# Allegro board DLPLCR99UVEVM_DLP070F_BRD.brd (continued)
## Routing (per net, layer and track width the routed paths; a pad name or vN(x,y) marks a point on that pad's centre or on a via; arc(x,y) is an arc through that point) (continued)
I2C_SCL_3P3V: length 123.7
  TOP w0.203: 115.04,13.7 114.54,14.2 114.54,17.05 114.43,17.17 R7.1 v1(112.81,18.78) ; 115.04,13.7 U17.8 ; 115.04,13.7 114.98,13.64 114.93,13.64 114.22,12.93 J5.1 ; v1(126.18,109.83) 126.66,110.31 126.66,110.51 127.93,111.78 127.93,113.31 127.17,114.07 J2.14
  LY4-SIG w0.165: v1(112.81,18.78) 116.26,18.78 128.19,30.71 128.19,90.63 127.52,91.29 127.52,107.42 126.18,108.76 v1(126.18,109.83)
I2C_SDA_3P3V: length 120.9
  TOP w0.203: v1(125.82,110.84) 125.82,112.39 126.79,113.36 126.79,114.83 126.67,114.95 J2.15 ; J5.2 115.47,10.28 114.85,10.9 114.85,12.75 115.16,13.05 115.43,13.05 115.43,13.05 U17.7 118.76,13.05 119.35,13.64 119.35,16.71 119.38,16.75 R6.1 v1(119.38,18.93)
  LY4-SIG w0.165: v1(119.38,18.93) 129.61,29.16 129.61,106.32 126.99,108.94 126.99,110.59 126.74,110.84 v1(125.82,110.84)
LATCH_CLEAR_Z: length 29.3
  TOP w0.203: R56.1 108.98,94 108.6,94.39 U18.6 106.96,94.39 v1(106.44,93.88)
  LY6-SIG w0.119: v1(106.44,93.88) 107.2,94.64 107.2,110.01 110.25,113.05 v1(111.9,113.05)
  BOTTOM w0.203: v1(111.9,113.05) 112.18,113.33 J4.8
LS_CLK_N: length 128.3
  TOP w0.127: J1.11 84.86,115.32 84.79,115.25 84.79,115.1 84.87,115.02 84.87,114.16 84.6,113.89 84.6,111.99 84.88,111.71 86.13,111.71 86.5,111.33 86.5,110.9 86.63,110.77 86.71,110.77 v1(87.17,110.31)
  LY4-SIG w0.127: v1(87.75,14.23) 87.19,14.79 87.19,15.05 93.84,21.71 93.84,22.48 93.6,22.73 93.6,23.59 93.84,23.84 93.84,25.22 93.61,25.45 93.61,25.86 93.84,26.1 93.84,27.76 93.61,27.99 93.61,28.4 93.84,28.64 93.84,30.05 93.44,30.45 93.44,31.09 93.82,31.46 93.82,32.62 93.54,32.9 93.54,33.83 101.24,41.53 101.24,54.38 104.36,57.5 104.36,84.59 103.05,85.9 103.05,93.55 101.18,95.42 99.04,95.42 97.41,93.79 93.59,93.79 89.63,97.74 89.63,104.26 86.56,107.34 86.56,109.87 86.69,110 86.86,110 86.88,110.02 86.88,110.02 v1(87.17,110.31)
  BOTTOM w0.508: U16.A25 v1(87.75,14.23)
LS_CLK_P: length 126.7
  TOP w0.127: J1.12 84.36,115.32 84.53,115.15 84.53,115 84.61,114.92 84.61,114.27 84.34,114 84.34,111.88 84.77,111.45 86.02,111.45 86.25,111.23 v1(86.25,110.31)
  LY4-SIG w0.127: v1(86.48,15.5) 87.2,15.5 93.53,21.84 93.53,22.36 93.29,22.6 93.29,23.72 93.53,23.97 93.53,25.09 93.3,25.33 93.3,25.99 93.53,26.23 93.53,27.63 93.3,27.87 93.3,28.53 93.53,28.77 93.53,29.93 93.13,30.33 93.13,31.22 93.51,31.59 93.51,32.49 93.23,32.77 93.23,33.96 100.93,41.66 100.93,54.51 104.05,57.63 104.05,84.46 102.74,85.77 102.74,93.42 101.05,95.11 99.17,95.11 97.54,93.48 93.46,93.48 89.32,97.61 89.32,104.13 86.25,107.21 v1(86.25,110.31)
  BOTTOM w0.508: U16.B24 v1(86.48,15.5)
LS_RDATA_A: length 140.2
  TOP w0.203: J1.8 v1(86.36,114.63)
  LY4-SIG w0.165: v1(86.36,114.63) 86.36,116.55 87.11,117.3 93.22,117.3 93.97,118.05 93.97,120 93.22,120.75 84.07,120.75 83.35,120.04 83.35,113.51 81.6,111.76 81.6,111.5 80.51,110.41 80.51,107.31 83.51,104.32 83.51,90.3 95.37,78.43 95.37,58.44 93.95,57.02 93.95,54.46 97.27,51.13 97.27,42.65 90.82,36.19 90.82,23.52 87.88,20.58 v1(86.48,20.58)
  BOTTOM w0.508: U16.F24 v1(86.48,20.58)
LS_RDATA_B: length 135.1
  TOP w0.203: J2.7 130.67,115.24 130.83,115.09 130.83,113.64 130.24,113.05 130.24,112.22 130.52,111.94 130.73,111.94 v1(131.26,111.4)
  LY6-SIG w0.119: v1(131.26,111.4) 130.31,111.4 129.91,111.01 129.91,110.26 132.25,107.92 132.25,88.29 130.67,86.71 130.67,69.21 111.19,49.73 108.14,49.73 105.15,46.73 98.56,46.73 95.96,44.14 95.09,44.14 93.77,45.46 89.63,45.46 89.2,45.03 89.2,44.19 91.07,42.32 91.07,30.08 93.39,27.76 93.39,23.98 91.96,22.55 91.81,22.55 89.02,19.77 v1(89.02,18.04)
  BOTTOM w0.508: U16.D26 v1(89.02,18.04)
LS_RDATA_C: length 129.5
  TOP w0.203: J2.8 v1(130.17,114.63)
  LY6-SIG w0.119: v1(94.1,20.58) 95.3,20.58 98.24,23.52 98.24,27.74 92.34,33.63 92.34,43 93.35,44.01 94.39,44.01 94.86,43.53 96.05,43.53 98.62,46.1 105.71,46.1 106.9,47.29 109.64,47.29 110.28,47.93 111.22,47.93 131.44,68.15 131.44,85.72 133.11,87.4 133.11,110.24 131.37,111.99 130.57,111.99 129.51,113.05 129.51,113.97 130.17,114.63 v1(130.17,114.63)
  BOTTOM w0.508: U16.F30 v1(94.1,20.58)
LS_RDATA_D: length 132.5
  TOP w0.203: J2.9 129.67,115.08 129.61,115.01 129.61,112.93 129.86,112.67 129.86,112.09 130.17,111.78 130.17,111.32 130.55,110.95 v1(130.55,110.57)
  LY6-SIG w0.119: v1(130.55,110.57) 132.6,108.51 132.6,87.73 131.03,86.16 131.03,69.04 111.29,49.3 108.25,49.3 105.29,46.35 98.52,46.35 96.01,43.84 94.96,43.84 94.23,44.58 93.46,44.58 91.76,42.87 91.76,41.53 92.1,41.19 92.1,31.82 94.73,29.18 94.73,22.33 93.62,21.21 90.97,21.21 89.5,19.73 89.5,18.77 90.29,17.98 v1(90.29,16.77)
  BOTTOM w0.508: U16.C27 v1(90.29,16.77)
LS_WDATA_N: length 127.8
  TOP w0.127: v1(82.31,110.31) 82.01,110.62 82.01,112.09 83.24,113.32 83.24,115.2 83.36,115.32 J1.14
  LY4-SIG w0.127: v1(82.31,110.31) 81.81,109.81 81.81,108.35 87.82,102.34 87.82,93.07 99.69,81.2 99.69,42.45 92.2,34.95 92.2,34.11 92.47,33.83 92.47,32.87 92.2,32.59 92.2,31.57 92.47,31.29 92.47,30.17 92.2,29.9 92.2,28.7 92.37,28.53 92.37,27.87 92.2,27.69 92.2,26.16 92.37,25.99 92.37,25.33 92.2,25.15 92.2,23.62 92.37,23.45 92.37,22.79 92.2,22.61 92.2,22.36 85.97,16.13 85.97,15.14 87.63,13.49 90.59,13.49 90.94,13.84 90.94,14.58 90.34,15.19 89.5,15.19 89.02,14.71 89.02,14.43 89.22,14.23 v1(90.29,14.23)
  BOTTOM w0.508: U16.A27 v1(90.29,14.23)
LS_WDATA_P: length 127.3
  TOP w0.127: J1.15 82.86,115.32 82.98,115.2 82.98,113.42 81.75,112.19 81.75,110.67 v1(81.39,110.31)
  LY4-SIG w0.127: v1(81.39,110.31) 81.39,109.83 81.5,109.73 81.5,108.22 87.51,102.21 87.51,92.94 99.38,81.08 99.38,42.58 91.89,35.08 91.89,33.98 92.16,33.7 92.16,32.99 91.89,32.72 91.89,31.44 92.16,31.16 92.16,30.3 91.89,30.03 91.89,28.58 92.06,28.4 92.06,27.99 91.89,27.82 91.89,26.04 92.06,25.86 92.06,25.45 91.89,25.28 91.89,23.5 92.06,23.32 92.06,22.91 91.89,22.74 91.89,22.48 85.66,16.26 85.66,15.02 87.5,13.18 90.72,13.18 91.25,13.71 91.25,14.71 90.47,15.5 v1(89.02,15.5)
  BOTTOM w0.508: U16.B26 v1(89.02,15.5)
MBRST0: length 110
  TOP w0.203: J9.1 v1(3.32,13.36)
  LY4-SIG w0.165: v1(3.32,13.36) 6.37,10.31 44.57,10.31 47.11,7.77 66.13,7.77 68.98,10.62 68.98,14.12 67.96,15.14 67.96,15.75 74.9,22.68 77.11,22.68 78.22,23.8 87.72,23.8 88.49,24.56 88.49,27.66 v1(90.29,29.47)
  BOTTOM w0.508: U16.N27 v1(90.29,29.47)
MBRST1: length 98.5
  TOP w0.203: J9.2 v1(16.93,15.9)
  LY4-SIG w0.165: v1(90.29,32.01) 87.67,29.39 87.67,25.09 86.94,24.36 78.1,24.36 77.31,23.57 75.18,23.57 67.58,15.98 67.58,14.98 68.47,14.1 68.47,11.02 65.88,8.43 47.06,8.43 43.58,11.91 20.92,11.91 v1(16.93,15.9)
  BOTTOM w0.508: U16.R27 v1(90.29,32.01)
MBRST2: length 66.5
  TOP w0.203: J9.3 v1(3.32,18.44)
  LY2-SIG w0.145: v1(3.32,18.44) 39.82,18.44 44.82,23.44 52.47,23.44 58.49,29.46 59.36,29.46 59.36,29.47 v1(59.81,29.47)
  BOTTOM w0.508: U16.N5 v1(59.81,29.47)
MBRST3: length 77.6
  TOP w0.203: J9.4 v1(16.93,20.98)
  LY4-SIG w0.165: v1(16.93,20.98) 24.17,13.74 52.49,13.74 55.54,10.69 64.56,10.69 66.82,12.95 66.82,18.69 59.81,25.7 v1(59.81,26.93)
  BOTTOM w0.508: U16.L5 v1(59.81,26.93)
MBRST4: length 121
  TOP w0.203: J9.5 v1(3.32,23.52)
  LY6-SIG w0.119: v1(3.32,23.52) 3.32,21.03 22.17,2.18 68.85,2.18 71.01,4.34 71.01,8.13 76.93,14.05 76.93,20.03 78.11,21.21 88.41,21.21 89.8,22.6 89.8,26.44 v1(90.29,26.93)
  BOTTOM w0.508: U16.L27 v1(90.29,26.93)
MBRST5: length 85.5
  TOP w0.203: J9.6 v1(16.93,26.06)
  LY2-SIG w0.145: v1(90.29,24.39) 87.08,24.39 87.04,24.43 63.52,24.43 62.48,25.48 62.48,29.64 61.94,30.17 56.94,30.17 54.65,27.89 45.74,27.89 43.91,26.06 v1(16.93,26.06)
  BOTTOM w0.508: U16.J27 v1(90.29,24.39)
MBRST6: length 64.3
  TOP w0.203: J9.7 v1(3.32,28.6)
  LY2-SIG w0.145: v1(3.32,28.6) 41.52,28.6 42.08,28.04 44.7,28.04 45.48,28.83 52.87,28.83 56.63,32.59 58.08,32.59 58.66,32.01 v1(59.81,32.01)
  BOTTOM w0.508: U16.R5 v1(59.81,32.01)
MBRST7: length 79.1
  TOP w0.203: J9.8 v1(16.93,31.14)
  LY4-SIG w0.165: v1(16.93,31.14) 22.5,25.58 22.5,22.55 29.56,15.49 51.38,15.49 55.29,11.58 64.23,11.58 65.9,13.26 65.9,15.02 65.64,15.28 65.64,15.72 65.98,16.05 65.98,17.32 59.81,23.49 v1(59.81,24.39)
  BOTTOM w0.508: U16.J5 v1(59.81,24.39)
MBRST8: length 137.8
  TOP w0.203: J9.9 v1(3.32,33.68)
  LY6-SIG w0.119: v1(90.29,34.55) 88.89,33.15 88.89,23.77 87.57,22.45 76.99,22.45 76.52,21.98 76.52,14.27 69.71,7.47 69.71,4.44 68.5,3.22 51.02,3.22 49.7,4.55 22.85,4.55 8.6,18.79 8.6,32.38 7.31,33.68 v1(3.32,33.68)
  BOTTOM w0.508: U16.U27 v1(90.29,34.55)
MBRST9: length 50.7
  TOP w0.203: J9.10 v1(16.93,36.22)
  LY2-SIG w0.145: v1(16.93,36.22) 41.44,36.22 42.03,35.64 44.77,35.64 45.86,36.73 53.79,36.73 55.39,35.13 56.66,35.13 58.61,37.08 59.36,37.08 59.36,37.09 v1(59.81,37.09)
  BOTTOM w0.508: U16.W5 v1(59.81,37.09)
MBRST10: length 62.3
  TOP w0.203: J9.11 v1(3.32,38.76)
  LY2-SIG w0.145: v1(3.32,38.76) 3.77,38.76 4.05,39.04 57.57,39.04 58.16,39.63 v1(59.81,39.63)
  BOTTOM w0.508: U16.AA5 v1(59.81,39.63)
MBRST11: length 138.7
  TOP w0.203: J9.12 v1(16.93,41.3)
  LY6-SIG w0.119: v1(16.93,41.3) 14.44,38.81 14.44,15.87 25.09,5.23 49.7,5.23 51.05,3.89 54.97,3.89 55.29,4.2 55.29,5.61 55.62,5.94 67.58,5.94 76.12,14.48 76.12,23.23 76.61,23.72 87.39,23.72 88.46,24.79 88.46,35.25 v1(90.29,37.09)
  BOTTOM w0.508: U16.W27 v1(90.29,37.09)
MBRST12: length 107.6
  TOP w0.203: J9.13 v1(3.32,43.84)
  LY2-SIG w0.145: v1(3.32,43.84) 2.05,45.11 2.05,49.43 2.71,50.09 36.97,50.09 41.24,45.82 52.11,45.82 55.24,42.7 61.87,42.7 61.99,42.57 81.8,42.57 85.87,46.63 87.22,46.63 90.29,43.55 v1(90.29,42.17)
  BOTTOM w0.508: U16.AC27 v1(90.29,42.17)
MBRST13: length 101.3
  TOP w0.203: J9.14 v1(16.93,46.38)
  LY4-SIG w0.165: v1(59.81,34.55) 59.81,33.66 59.2,33.04 59.2,23.39 65.5,17.09 65.5,16.01 65.33,15.84 65.33,15.15 65.47,15.01 65.47,13.36 64.23,12.11 58.13,12.11 53.79,16.46 48.35,16.46 47.11,17.7 31.54,17.7 25.57,23.67 25.57,37.74 v1(16.93,46.38)
  BOTTOM w0.508: U16.U5 v1(59.81,34.55)
MBRST14: length 65.5
  TOP w0.203: J9.15 v1(3.32,48.92)
  LY2-SIG w0.145: v1(3.32,48.92) 9.19,43.05 17.97,43.05 19.47,41.55 40.33,41.55 40.68,41.9 41.4,41.9 41.74,41.55 59.2,41.55 v1(59.81,42.17)
  BOTTOM w0.508: U16.AC5 v1(59.81,42.17)
MBRST15: length 143.6
  TOP w0.203: J9.16 v1(16.93,51.46)
  LY6-SIG w0.119: v1(16.93,51.46) 20.08,48.31 20.08,13.92 26.69,7.31 51.88,7.31 52.47,6.73 67.83,6.73 75.63,14.53 75.63,23.33 76.33,24.03 87.01,24.03 88.03,25.04 88.03,37.36 v1(90.29,39.63)
  BOTTOM w0.508: U16.AA27 v1(90.29,39.63)
P1P8V_LDO: length 20.7
  TOP w0.254: U18.8 107.82,96.33 C179.2
  TOP w0.381: R12.2 v1(114.19,100.1) ; U7.5 v1(116.65,94) ; U9.5 v1(133.9,94)
  TOP w0.508: 43.23,102.1 TP17.1 ; TP17.1 45.45,102.1 ; TP17.1 45.45,99.88 ; TP17.1 43.23,99.88 ; C181.2 42.42,93.08 R55.2 42.42,98.18 v1(42.82,98.58) ; R56.2 v1(111.65,94) ; R53.2 v1(102.11,92.87) ; R54.2 v1(111.65,95.27) ; C179.2 v1(108.73,96.54)
P3P3V: length 21.3
  TOP w0.203: v1(12.26,90.25) 12.7,89.81 U6.2 ; C17.2 13.39,91.41 U6.1 ; U24.6 88.29,91.02 v1(87.65,91.67) ; U25.6 67.97,99.28 v1(67.33,99.92) ; v1(12.59,88.29) 13.11,88.81 U6.4
  TOP w0.254: v1(110.38,14.1) 110.78,13.7 U17.1
  TOP w0.381: R7.2 v1(111.76,16.32) ; v1(120.79,16.1) 120.43,16.47 R6.2 ; R39.2 v1(91.67,104.68) ; C175.2 v1(111.24,15.26)
  TOP w0.508: C17.2 v1(13.34,92.42) ; J5.3 v1(116.72,8.02)
  BOTTOM w0.508: C195.2 v1(87.65,91.67) ; C197.2 v1(67.33,99.92) ; R60.2 90.36,87.65 v1(90.67,87.96) ; R63.2 70.04,95.91 v1(70.35,96.21)
  vias: v1(18.3,99.08) v1(20.72,98.83) v1(20.84,99.97) v1(23.26,98.7) v1(25.54,98.83) v1(27.45,98.83) v1(29.1,99.08) v1(89.93,108.86) v1(91.08,108.86) v1(92.22,108.86) v1(93.36,110.01) v1(93.36,108.86) v1(133.62,108.86) v1(134.76,108.86) v1(135.91,108.86) v1(137.05,110.01) v1(137.05,108.86)
POWERGOOD: length 135.6
  TOP w0.203: U7.6 115.54,101.49 114.95,102.08 114.68,102.08 114.61,102.14 R12.1 ; U7.6 118.01,94.95 118.33,95.27 R21.2 ; U7.6 U7.1 ; v1(114.18,111.95) 114.18,111.19 113.3,110.31 113.3,109.12 114.19,108.23 TP5.1 R12.1 ; U25.2 v1(68.47,96.95) ; R21.2 119.77,96.29 127.14,96.29 128.48,94.95 U9.1 U9.6 ; R21.2 118.75,94.26 119.27,93.74 D1.2 ; R12.1 v1(113.14,102.14) ; J2.12 128.17,115.07 128.39,114.85 128.39,113.95 128.31,113.87 128.31,111.58 127.07,110.34 127.07,109.96 v1(128.06,108.96) ; U24.2 v1(88.79,88.7)
  LY2-SIG w0.145: v1(114.18,111.95) 114.98,111.15 115.71,111.15 117.9,108.96 v1(128.06,108.96) ; v1(68.47,96.95) 69.13,97.61 82.44,97.61 v1(85.54,100.71) 86.25,100.71 94.84,109.3 105.99,109.3 v1(113.14,102.14)
  LY4-SIG w0.165: v1(88.79,88.7) 88.79,89.86 88.38,90.27 86.88,90.27 85.95,91.21 85.95,98.63 85.54,99.03 v1(85.54,100.71)
SW: length 18.9
  TOP w0.381: C26.2 v1(22.75,82.83)
  TOP w0.508: v1(8.14,85.27) 9.44,83.97 L2.2
  BOTTOM w0.635: v1(22.75,82.83) 20.84,82.83 18.41,85.27 v1(8.14,85.27)
V_BIAS: length 11.9
  TOP w0.381: R37.2 v1(97.04,102.72) ; R20.2 v1(128.27,91.83) ; C174.2 v1(46.13,18.67)
  BOTTOM w0.508: U16.D4 v1(58.54,18.04) ; C190.2 43.73,18.41 44.34,17.8 45.48,17.8 46.13,18.45 v1(46.13,18.67) ; v1(43.07,47.01) 42.46,46.4 C189.2 ; U16.AE3 v1(57.27,44.71) ; U16.AD4 v1(58.54,43.44)
  vias: v1(47.26,43.46) v1(48.12,44.17)
V_BIAS_CPI: length 22.4
  TOP w0.203: R41.2 13.24,68.1 v1(14.37,68.1) ; C38.2 C37.2 23.75,68.08 C36.1 23.38,68.48 22.75,69.11 20.84,69.11 20.34,68.6 20.34,68.35 20.03,68.05 D9.2 19.57,69.11 v1(19.45,69.24) 18.81,69.87 18.81,72.41 17.9,73.33 U10.16
  BOTTOM w0.203: v1(19.45,69.24) 18.43,69.24 17.8,68.6 14.88,68.6 v1(14.37,68.1)
V_OFFSET: length 18.7
  TOP w0.381: R18.2 v1(111.13,91.88) ; R31.2 v1(101.49,101.45) ; C139.2 v1(104.14,43.61)
  TOP w0.508: v1(21.86,66.83) 21.48,67.21 D7.1
  LY6-SIG w0.508: v1(15.38,63.4) 17.54,65.56 20.97,65.56 21.86,66.45 v1(21.86,66.83)
  BOTTOM w0.508: U16.AD26 v1(89.02,43.44) ; U16.F4 v1(58.54,20.58) ; U16.F26 v1(89.02,20.58) ; U16.H4 v1(58.54,23.12) ; U16.AE5 v1(59.81,44.71)
V_RESET: length 15.6
  TOP w0.381: C162.2 v1(51.21,55.5) ; U11.2 v1(108.34,100.55) ; R26.1 126.78,91.4 v1(126.15,92.02) ; C160.2 57.18,4.85 v1(57.9,4.85) ; U8.2 v1(121.2,94) ; R33.2 v1(105.03,105.32) ; C163.2 v1(49.31,53.59)
  BOTTOM w0.508: U16.D6 v1(61.08,18.04) ; U16.AF4 v1(58.54,45.98) ; v1(57.9,4.85) 57.29,4.85 56.91,4.47 56.91,3.2 57.27,2.84 C187.2 ; U16.E5 v1(59.81,19.31) ; U16.AG5 v1(59.81,47.25)
  vias: v1(30.6,85.37) v1(30.65,86.38) v1(30.65,84.23) v1(33.8,85.27) v1(33.88,86.38) v1(33.9,84.17)
N16783807: length 4
  TOP w0.203: U9.4 132.68,91.5 R27.2 R24.1
N16783825: length 4
  TOP w0.203: U9.3 129.98,92.26 129.32,91.59 R20.1 R24.2
N16783989: length 4
  TOP w0.203: U8.4 125.06,91.5 R26.2 R23.1
N16784029: length 4
  TOP w0.203: R23.2 R19.1 122.36,91.5 U8.3
N16784057: length 5.4
  TOP w0.203: R21.1 121.33,95.27 121.65,94.95 U8.1 U8.6
N16784127: length 4
  TOP w0.203: U7.3 112.84,91.5 R18.1 R22.2
N16784131: length 4
  TOP w0.203: U7.4 115.54,91.5 R25.2 R22.1
N16784325: length 18.5
  TOP w0.203: U15.2 104.97,98.75 104.66,98.45 99.84,98.45 98.82,99.47 ; 98.82,99.47 95.52,99.47 95.27,99.71 U13.1 95.27,100.5 94.21,101.56 U12.3 R39.1 ; 98.82,99.47 99.08,99.72 99.08,99.91 99.08,99.92 U14.1
N16784355: length 1.9
  TOP w0.203: R37.1 R40.2
N16784357: length 2.3
  TOP w0.203: U13.3 95.77,103.01 R40.1
N16784417: length 5.8
  TOP w0.254: U10.13 17.31,71.38 17.54,71.14 v1(17.54,70.51) ; U10.4 v1(9.36,76.58)
  TOP w0.381: C20.2 9.12,76.34 v1(9.36,76.58)
  TOP w0.508: C19.2 17.21,69.87 17.54,70.2 v1(17.54,70.51)
  vias: v1(15.16,79.63) v1(16.53,79.65)
N16784489: length 2.1
  TOP w0.203: D8.2 U14.3
N16784491: length 1.9
  TOP w0.203: D8.1 101.46,105.92 R38.1
N16784593: length 28.4
  TOP w0.254: v1(9.03,73.66) 9.36,73.33 U10.9
  TOP w0.381: R48.1 6.23,91.07 5.99,90.83 5.59,90.83 C177.2 C25.2 R28.2 4.83,85.46 D2.2 3.81,84.44 C23.2 3.81,80.61 4.33,80.09 C22.2 4.33,79.86 3.29,78.82 3.29,76.3 6.8,72.79 7.76,72.79 8.03,73.06 C24.2 9.01,73.68 v1(9.03,73.66)
N16784602: length 15.6
  TOP w0.203: U10.1 9.9,78.53 v1(9.57,78.87) ; v1(8.45,87.65) 8.44,87.64 R29.2 7.27,87.4 R28.1 C25.1
  BOTTOM w0.203: v1(9.57,78.87) 9.57,81.91 7.38,84.1 7.38,86.59 v1(8.45,87.65)
N16784669: length 4
  TOP w0.203: C26.1 24.19,80.78 24.23,80.75 D3.2 D4.1
N16784699: length 4.1
  TOP w0.203: C31.1 26.14,76.34 26.1,76.3 D4.2 24.65,75.62 24.68,75.6 24.68,75.28 25.21,74.75 D5.1
N16784701: length 4
  TOP w0.203: D6.1 22.78,73.85 22.83,73.9 D5.2 C30.1
N16784732: length 17.7
  TOP w0.254: C29.2 C28.2 ; C28.2 C27.1 ; C28.2 24.78,85.11 25.42,85.75 26.31,85.75 26.69,85.37 R49.1 ; C28.2 24.65,85 D3.1 24.65,82.07 25.54,81.18 25.54,78.13 24.91,77.49 24.15,77.49 23.63,78.01 R30.2
N16784789: length 3
  TOP w0.203: U10.18 18.96,74.63 19.27,74.32 C30.2
N16784866: length 6.5
  TOP w0.203: R30.1 22.31,77.42 20.25,77.42 R32.2 19.15,76.74 18.99,76.58 U10.21
N16784882: length 4.8
  TOP w0.203: U10.20 18.93,75.93 19.15,75.7 R32.1 C33.2
N16784896: length 3.5
  TOP w0.203: C35.2 18.12,73.98 U10.17
N16784898: length 4.3
  TOP w0.203: U10.12 10.91,69.53 R42.2 R41.1
N16784904: length 2
  TOP w0.203: U6.6 v1(16.61,89.31)
  BOTTOM w0.203: C18.2 15.68,89.31 v1(16.61,89.31)
N16784908: length 4.8
  TOP w0.203: D7.2 21.48,71.66 C35.1 19.57,71.26 D9.1
N16785040: length 1.4
  TOP w0.203: R36.1 20.84,78.67 20.73,78.55 C32.2
N16785042: length 3.3
  TOP w0.203: U10.22 18.79,77.23 C32.1
N16785060: length 3.4
  TOP w0.203: C34.1 9.78,77.88 U10.2
N16795774: length 2.4
  TOP w0.203: U11.3 107.84,102.91 107.47,103.28 107.39,103.28 107.2,103.46 R34.2
N16795788: length 5.7
  TOP w0.203: U11.1 106.92,101.69 106.52,102.08 U15.3 R33.1
N16797776: length 1.9
  TOP w0.203: R34.1 R35.2
N16804439: length 18.5
  LY2-SIG w0.145: v1(91.56,20.58) 92.78,20.58 93.39,21.18 104.61,21.18 v1(106.68,23.25)
  BOTTOM w0.203: R45.1 v1(106.68,23.25)
  BOTTOM w0.508: U16.F28 v1(91.56,20.58)
N16806468: length 4.4
  TOP w0.127: U17.3 111.13,12.4 110.94,12.6 110.38,12.6 110.06,12.28 108.72,12.28 108.63,12.19 R47.2
N16806470: length 4.4
  TOP w0.127: R46.2 108.63,12.63 108.72,12.53 109.96,12.53 110.27,12.85 110.94,12.85 111.13,13.05 U17.2
N16806960: length 31.4
  TOP w0.127: R46.1 107.05,12.63 106.96,12.53 106.31,12.53 106,12.22 105.86,12.22 105.77,12.31 105.77,12.52 105.68,12.61 C176.2 104.92,12.61 104.83,12.52 104.83,12.31 104.74,12.22 104.05,12.22 v1(103.72,12.55)
  LY6-SIG w0.107: v1(103.72,12.55) 103.42,12.24 93.7,12.24 92.71,13.23 90.3,13.23 87.21,16.32 87.21,17.19 87.59,17.57 87.59,18.35 85.66,20.28 84.7,20.28 84.53,20.11 84.41,20.11 v1(83.94,20.58)
  BOTTOM w0.508: U16.F22 v1(83.94,20.58)
N16807032: length 31.2
  TOP w0.127: R47.1 107.05,12.19 106.96,12.28 106.42,12.28 106.1,11.96 105.86,11.96 105.77,11.87 105.77,11.66 105.68,11.57 C176.1 104.92,11.57 104.83,11.66 104.83,11.87 104.74,11.96 104.05,11.96 v1(103.72,11.63)
  LY6-SIG w0.107: v1(85.21,19.31) 84.75,19.78 84.75,19.89 84.83,19.97 85.53,19.97 87.28,18.22 87.28,17.7 86.9,17.31 86.9,16.19 90.17,12.92 92.58,12.92 93.57,11.93 103.42,11.93 v1(103.72,11.63)
  BOTTOM w0.508: U16.E23 v1(85.21,19.31)
N16928315: length 7.5
  TOP w0.203: R50.2 17.67,67.83 17.67,68.86 18.18,69.37 18.18,72.41 17.91,72.68 U10.15
N16943816: length 2.3
  TOP w0.203: U18.2 104.04,94.89 R53.1
N16945352: length 2.1
  TOP w0.203: R54.1 109.35,94.89 U18.7
N16947306: length 2.8
  TOP w0.635: U19.3 40.11,95.6 R55.1
N17048439: length 8.9
  TOP w0.203: 82.8,94.54 87.09,94.54 88.79,92.84 U24.5
N17048467: length 8.1
  TOP w0.203: U24.3 89.29,89.06 89.43,88.92 89.43,88.3 88.79,87.65 R59.2 ; R59.2 87.25,86.54 C194.1 ; R59.2 R58.1
N17053433: length 8.6
  TOP w0.203: 62.24,102.34 66.69,102.34 68.47,100.56 U25.5
N17053493: length 8.1
  TOP w0.203: R64.1 R65.2 ; R64.1 68.47,95.91 69.11,96.55 69.11,97.17 68.97,97.31 U25.3 ; R64.1 66.93,94.79 C198.1
N167843971: length 1.5
  TOP w0.203: R38.2 R31.1

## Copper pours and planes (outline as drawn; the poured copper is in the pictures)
GND on TOP: 0.63,0.63 0.63,124.37 149.36,124.37 149.36,0.63 ; 9 cut-outs
GND on LY2-SIG: 149.36,0.63 0.63,0.63 0.63,124.37 149.36,124.37 ; 11 cut-outs
GND on LY3-GND, LY5-GND, LY7-GND: 149.36,0.63 0.63,0.63 0.63,124.37 149.36,124.37
GND on LY4-SIG: 0.63,0.63 114.57,0.63 114.57,0.63 149.36,0.63 149.36,124.37 0.63,124.37 ; 24 cut-outs
GND on LY6-SIG: 149.36,0.63 0.63,0.63 0.63,124.37 149.36,124.37 ; 33 cut-outs
VDD_DMD on TOP: 90.69,39.39 90.06,38.76 90.06,24.15 91.33,22.88 100.98,22.88 103.27,25.17 106.32,25.17 107.2,26.06 107.2,37.49 106.57,38.12 93.23,38.12 91.96,39.39
VDD_DMD on BOTTOM: 37.35,1.93 109.11,1.93 109.11,18.44 142.76,18.44 142.76,89.56 95.14,89.56 89.42,83.84 37.35,83.84 ; 3 cut-outs
VDD_DMD on LY2-SIG: 88.15,20.34 88.15,22.88 87.52,23.52 55.77,23.52 53.86,21.61 45.61,21.61 44.34,20.34 44.34,6.37 48.78,1.93 95.14,1.93 95.77,2.56 95.77,7.01 91.96,10.82 79.26,10.82 76.09,13.99 76.09,19.71 76.72,20.34 77.99,20.34 78.63,19.71 78.63,17.17 82.44,13.36 93.23,13.36 95.77,15.9 95.77,16.92 95.27,17.42 91.08,17.42
VDD_DMD on LY4-SIG: 53.74,48.08 57.62,48.08 63.14,42.57 86.5,42.57 87.52,41.55 87.52,38.12 88.79,36.85 90.69,36.85 96.41,42.57 96.41,49.55 92.6,53.36 87.52,53.36 86.12,51.97 54.37,51.97 53.74,51.33
VDDA_DMD on TOP: 59.91,93.22 59.91,90.55 61.33,89.13 64.56,89.13 65.85,87.83 65.85,85.95 68.06,83.74 73.52,83.74 74.39,84.61 74.39,89.48 73.17,90.7 69.87,90.7 68.72,91.85 68.72,93.12 68.19,93.65 60.34,93.65
VDDA_DMD on TOP: 72.66,23.52 63.26,23.52 60.6,20.85 60.6,20.6 61.61,19.58 63.14,19.58 63.77,18.95 63.77,8.03 60.98,5.23 60.6,5.23 60.6,4.98 60.85,4.72 67.96,4.72 70.5,7.26 70.5,16.15 73.17,18.82 73.17,23.01
VDDA_DMD on TOP: 70.76,42.95 86.76,42.95 88.03,44.22 99.2,44.22 100.47,45.49 103.27,45.49 103.52,45.24 104.41,45.24 104.54,45.36 104.54,52.09 103.9,52.73 103.9,53.87 103.14,54.63 103.14,56.03 102.89,56.29 102.38,56.29 101.87,56.79 101.87,59.84 101.62,60.1 99.33,60.1 98.95,60.48 98.95,61.24 98.7,61.49 97.43,61.49 96.92,62 82.06,62 81.68,62.38 81.68,63.52 82.44,64.29 82.44,64.67 82.06,65.05 67.71,65.05 67.58,64.92 67.58,64.16 68.22,63.52 69.36,63.52 70.63,62.25 70.63,43.08
VDDA_DMD on BOTTOM: 86.88,23.77 87.9,22.76 87.9,22.63 89.42,22.63 92.09,25.3 92.09,26.06 91.58,26.57 88.54,26.57 88.15,26.95 88.15,36.73 91.96,40.54 91.96,41.17 91.46,41.68 89.93,41.68 89.68,41.43 88.54,41.43 86.88,43.08 86.88,43.84 86.5,44.22 82.95,44.22 81.93,45.24 81.93,46.25 81.55,46.63 79.9,46.63 79.65,46.38 79.65,45.87 77.61,43.84 71.14,43.84 70.76,43.46 70.76,42.7 71.64,41.81 85.87,41.81 86.88,40.79 86.88,25.68 86,24.79 64.41,24.79 63.26,23.65 63.26,22.76 63.39,22.63 66.06,22.63 67.58,21.11 72.66,21.11 72.91,21.36 72.91,22.38 73.17,22.63 73.17,23.52 73.42,23.77
VDDA_DMD on LY2-SIG: 71.14,43.08 79.39,43.08 83.84,47.52 87.01,47.52 90.69,43.84 90.69,40.66 91.33,40.03 91.96,40.03 92.6,40.66 93.87,40.66 95.14,39.39 95.14,29.87 91.33,26.06 91.33,25.55 94.63,22.25 104.16,22.25 107.97,26.06 111.01,26.06 112.28,24.79 112.92,24.79 113.55,25.42 113.55,27.96 109.11,32.41 109.11,41.3 108.47,41.93 103.39,41.93 102.76,42.57 102.76,44.47 103.39,45.11 107.2,45.11 109.11,47.01 109.11,79.53 99.71,88.92 69.74,88.92 68.47,87.65 68.47,65.56 71.26,62.76 77.49,62.76 79.14,61.11 79.14,57.17 70.88,48.92 70.88,43.33
P1P8V_LDO on TOP: 41.8,117.5 41.8,91.34 42.94,90.19 48.15,90.19 49.42,91.46 49.42,101.62 52.59,104.8 77.99,104.8 86.25,96.54 86.88,96.54 90.69,92.73 93.87,92.73 96.54,90.07 101.62,90.07 107.84,83.84 135.14,83.84 138.95,87.65 138.95,91.72 136.03,94.64 131.97,94.64 131.59,94.26 131.59,93.62 131.84,93.37 134.51,93.37 135.65,92.23 135.65,89.05 135.27,88.67 118.63,88.67 118.63,93.5 117.62,94.51 114.95,94.51 114.95,93.5 116.98,93.5 117.87,92.61 117.87,88.67 110.63,88.67 110.13,89.18 110.13,91.08 112.54,93.5 112.54,96.42 115.08,98.96 115.08,100.74 114.57,101.24 112.54,101.24 110,98.7 100.35,98.7 99.46,97.81 91.96,97.81 81.17,108.61 50.69,108.61 47.51,111.78 47.51,117.5
P3P3V on TOP: 89.3,110.77 89.3,108.61 89.55,108.36 94.12,108.36 94.38,108.61 94.38,110.13 93.74,110.77
P3P3V on TOP: 18.18,97.43 29.35,97.43 33.42,93.37 33.42,92.23 33.67,91.97 34.31,91.97 34.81,92.48 34.81,97.31 33.93,98.2 33.42,98.2 30.88,100.74 21.1,100.74 19.96,101.88 17.92,101.88 17.42,101.37 17.42,98.2
P3P3V on TOP: 132.99,110.77 132.99,108.61 133.24,108.36 137.81,108.36 138.07,108.61 138.07,110.13 137.43,110.77
P3P3V on BOTTOM: 11.32,85.75 89.42,85.75 93.87,90.19 143.4,90.19 143.4,17.17 109.74,17.17 109.74,2.56 147.84,2.56 148.48,3.2 148.48,107.97 145.3,111.15 7.51,111.15 6.87,110.51 6.87,90.19
SW on TOP: 6.47,74.88 9.8,74.88 10.05,75.13 11.55,75.13 11.65,75.23 11.65,75.92 11.52,76.05 9.97,76.05 9.82,75.89 7.54,75.89 7.33,76.1 7.33,82.02 7.59,82.27 11.02,82.27 11.29,82.55 11.29,85.06 11.28,85.08 11.28,85.38 10.96,85.7 6.75,85.7 5.88,84.83 5.88,75.46
V_BIAS on TOP: 45.86,17.17 58.56,17.17 58.94,17.55 58.94,18.44 58.56,18.82 46.5,18.82 45.86,18.19
V_BIAS on TOP: 43.58,42.57 58.69,42.57 59.07,42.95 59.07,44.35 56.28,47.14 49.22,47.14 47.78,48.58 44.58,48.58 43.83,49.33 43.83,51.97 31.77,64.03 31.77,67.97 31,68.73 28.72,68.73 28.72,67.59 27.45,66.32 14.62,66.32 14.3,66 14.3,65.49 16.65,63.14 24.91,63.14 40.4,47.65 40.4,45.74
V_BIAS on LY2-SIG: 55.59,43.2 58.82,43.2 59.07,43.46 59.07,44.86 52.47,51.46 50.94,51.46 39.89,62.51 39.89,77.37 52.72,90.19 87.72,90.19 100.09,102.56 101.69,102.56 116.09,88.16 128.03,88.16 129.3,89.43 129.3,91.85 128.67,92.48 127.78,92.48 127.27,91.97 127.27,90.96 126.64,90.32 116.6,90.32 101.62,105.31 97.3,105.31 84.34,92.35 50.31,92.35 37.48,79.53 37.48,61.31
V_BIAS on LY6-SIG: 44.72,18.08 47.29,18.08 47.9,18.69 47.9,29.87 46.12,31.65 46.12,39.39 48.91,42.19 48.91,44.47 48.4,44.98 44.97,44.98 43.58,43.59 43.58,19.23
V_OFFSET on TOP: outline of 93 points within 1.67,19.71 104.92,96.67
V_OFFSET on LY2-SIG: 103.65,42.57 114.82,42.57 117.62,45.36 117.62,86 101.36,102.26 100.85,102.26 100.09,101.5 100.09,99.21 114.82,84.48 114.82,45.62 113.55,44.35 103.78,44.35 103.27,43.84 103.27,42.95
V_RESET on TOP: 56.79,4.72 59.58,4.72 61.99,7.14 61.99,18.82 60.98,19.84 59.58,19.84 59.2,19.46 59.2,18.82 59.45,18.57 59.45,17.42 56.66,14.63 56.66,4.85
V_RESET on TOP: 28.46,82.45 37.99,82.45 47.2,73.24 47.2,69.05 50.44,65.81 50.44,63.63 46.06,59.25 46.06,53.13 49,50.19 51.32,50.19 52.47,49.05 55.01,49.05 58.31,45.74 58.69,45.74 60.21,47.27 60.21,48.16 53.05,55.32 53.05,59.66 54.37,60.98 54.37,69.49 52.47,71.4 52.47,75.34 38.62,89.18 28.46,89.18
V_RESET on LY2-SIG: 121.73,91.44 126.51,91.44 126.79,91.72 126.79,92.07 119.36,99.5 113.97,99.5 105.1,108.38 95.14,108.38 83.56,96.8 41.29,96.8 33.8,89.31 23.13,89.31 21.48,87.65 21.48,78.76 22.62,77.62 26.56,77.62 30.45,81.51 33.42,81.51 45.81,93.9 83.76,93.9 96.16,106.3 101.77,106.3 112.28,95.78 117.39,95.78
V_RESET on LY6-SIG: 60.6,17.3 61.74,17.3 62.78,18.34 62.78,22.6 60.47,24.92 60.47,47.52 59.96,48.03 58.94,48.03 57.8,46.89 57.8,20.09
N16772038 on BOTTOM: 107.54,112.14 110.33,112.14 111.27,113.08 111.27,116.74 111.14,116.86 108.68,116.86 108.58,116.76 108.58,114.86 107.51,113.79 107.51,112.17
N16773260 on TOP: 88.99,111.58 92.24,111.58 92.24,113.64 91.33,114.55 90.9,114.55 89.93,115.52 89.93,116.97 87.37,116.97 87.27,116.86 87.27,114.1 88.75,112.61 88.75,111.82
N16773766 on TOP: 133.06,111.48 136.11,111.48 136.11,113.59 135.14,114.55 134.71,114.55 133.75,115.52 133.75,116.97 131.18,116.97 131.08,116.86 131.08,114.22 131.54,113.77 132.43,113.77 132.66,113.54 132.66,111.89
N16774650 on BOTTOM: 63.72,112.14 66.51,112.14 67.45,113.08 67.45,116.74 67.33,116.86 64.86,116.86 64.76,116.76 64.76,114.86 63.69,113.79 63.69,112.17
N16775308 on TOP: 28.21,113.05 28.21,109.5 29.1,108.61 32.66,108.61 33.04,108.99 33.04,111.4 31.13,113.31 28.46,113.31
N16775316 on TOP: 15.38,114.32 18.05,114.32 18.81,115.09 20.46,115.09 21.1,115.72 21.1,116.23 20.59,116.74 15.38,116.74 15.26,116.61 15.26,114.45
N16775420 on TOP: 28.21,116.48 28.21,115.34 29.1,114.45 33.42,114.45 34.05,115.09 34.05,116.48 33.8,116.74 28.46,116.74
N16775848 on TOP: 24.02,101.37 26.56,101.37 27.83,102.64 37.1,102.64 39.13,104.67 39.13,115.21 37.48,116.86 35.83,116.86 35.45,116.48 35.45,106.07 34.05,104.67 28.72,104.67 28.08,105.31 21.48,105.31 19.57,107.21 16.27,107.21 15.89,106.83 15.89,104.55 17.42,103.02 22.37,103.02
N16784417 on TOP: 14.93,78.38 18.28,78.38 18.74,78.84 18.74,80.11 18.46,80.39 17.82,80.39 17.72,80.49 17.67,80.49 17.67,82.27 18.15,82.75 18.15,89.86 17.59,90.42 15.31,90.42 15.31,89.81 15.41,89.71 16.32,89.71 16.37,89.76 16.93,89.76 17.21,89.48 17.21,88.72 15.84,87.35 14.9,87.35 14.09,86.54 14.09,79.22
N16784417 on BOTTOM: 8.81,77.65 8.81,75.89 14.32,70.38 18.38,70.38 18.61,70.61 18.61,78.61 17.06,80.16 11.32,80.16
N17048439 on TOP: 84.47,91.34 86.38,91.34 87.24,92.2 87.98,92.2 88.26,91.92 89.15,91.92 89.45,92.23 89.45,93.04 86.71,95.78 80.1,95.78 79.21,94.89 79.21,93.85 80.51,92.56 84.34,92.56 84.34,91.46
N17048462 on TOP: 85.18,86.13 85.84,86.79 85.84,89.97 85.49,90.32 85.44,90.32 85.13,90.63 80.61,90.63 79.39,89.41 79.39,86.44 79.7,86.13
N17053433 on TOP: 66.06,99.59 66.92,100.46 67.66,100.46 67.94,100.18 68.83,100.18 69.13,100.48 69.13,103.38 68.44,104.06 60.04,104.06 59.33,103.35 59.33,101.24 60.98,99.59
N17053437 on TOP: 64.86,94.39 65.52,95.05 65.52,98.22 65.09,98.65 60.24,98.65 59.02,97.43 59.02,94.64 59.28,94.39
N167753000 on TOP: 16.78,108.61 20.59,108.61 21.23,109.24 21.23,113.05 20.97,113.31 18.3,113.31 16.53,111.53 16.53,108.86

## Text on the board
BOTTOM: LAYER 8 - SECONDARY SIDE
Ref Des/Assembly Bottom: ASSEMBLY - SECONDARY SIDE | 2   2
Ref Des/Silkscreen Bottom: FLEX CONNECTOR C | FLEX CONNECTOR D | LIBRA#  DLP-30179-02 | NOT FCC APPROVED FOR RESALE. | FOR EVALUATION ONLY. | TEXAS INSTRUMENTS | DLPLCR99EVM | PROJECT NUMBER: DLP019F | GPN: DLP991U
TOP: LAYER 1 - PRIMARY SIDE
Ref Des/Assembly Top: ASSEMBLY - PRIMARY SIDE | 1   2
Ref Des/Silkscreen Top: OFFSET | P3P3V | ALT 3.3V IN | BIAS | RESET | DMD PWR EN | FLEX CONNECTOR A | FLEX CONNECTOR B | PG | I2C | AMUX | DMUX | MBRST | DMD TP
LY2-SIG: LAYER 2 - SIGNAL
LY3-GND: LAYER 3 - GND PLANE
LY4-SIG: LAYER 4 - SIGNAL
LY5-GND: LAYER 5 - GND PLANE
LY6-SIG: LAYER 6 - SIGNAL
LY7-GND: LAYER 7 - PWR PLANE
PASTEMASK_TOP: SOLDERPASTE - PRIMARY SIDE
DIMENSION: CUTOUT | 50 OHMS SINGLE | ENDED +/-10% | 0.0057" | 0.0065 | 0.0047" | WIDTH/SPACING 100 OHMS | DIFFERENTIAL +/-10% | 0.0048/0.0074 | 0.0050/0.0072 | 0.0042/0.0080 | 6 | SOLDERPASTE - SECONDARY SIDE | FAB DRAWING | LAYER STACKUP | LAYER 1 - PRIMARY SIDE/GND FILL | LAYER 2 - SIGNAL | LAYER 3 - GND PLANE | LAYER 4 - SIGNAL | LAYER 5 - GND PLANE | LAYER 6 - SIGNAL | LAYER 7 - GND PLANE | LAYER 8 - SECONDARY SIDE/PWR FILL | *** | 10. MAXIMUM RATED VOLTAGE BETWEEN CONDUCTORS SHALL | BE 65 VOLTS PEAK. | 11. NO BREAKOUT ALLOWED ON PLATED THROUGH HOLES. | 12. FOIL OUTER OPTIONAL. | 13. INTERPRET DIMENSIONS IN ACCORDANCE WITH ASME | Y14.5M-1994 | 4. APPLY LPI SILKSCREEN OR EQUIVALENT BOTH SIDES PER THE ARTWORK. | COLOR: WHITE. | 14. TEARDROP VIAS AS NECESSARY. | 15. THIEVING IS NOT ALLOWED. | OVER A MINIMUM OF 50 MICROINCHES OF ELECTROLYTIC NICKEL. | 3. FABRICATION VENDOR IS ALLOWED TO INCREASE SOLDERMASK | COMPONENT PADS BY A MAXIMUM 1 MIL ON EACH SIDE OVER | THE COPPER PAD IN ORDER TO MEET TOOLING REQUIREMENTS | WHILE MAINTAINING WEBBING BETWEEN ADJACENT PADS. | MAXIMUM OF 50 MICROINCHES ELECTROLYTIC HARD GOLD | OVER ELECTROPLATED NICKEL (50 MIN MICROINCHES). | 6. PLATE INDICATED PAD AREAS WITH A MINIMUM OF 30, | 3. BOARD MATERIAL SHALL BE 180 Tg/340 Td ISOLA FR-370HR | OR EQUIVALENT, RoHS COMPLIANT AND LEAD FREE | ASSEMBLY CAPABLE.  BOARD MATERIAL SHALL | MEET OR EXCEED IPC-4101B. RoHS CERTIFICATE OF | CONFORMANCE SHALL BE DELIVERED WITH EACH LOT. | 7. INNER PLANE LAYERS TO BE 1/2 OZ. COPPER. | WORKMANSHIP SHALL CONFORM TO | OUTER LAYERS TO BE 1/2 OZ. COPPER + PLATING. | 1. ALL DIMENSIONS ARE IN INCHES UNLESS | OTHERWISE NOTED.  ALL BOARD | OUTLINE DIMENSION TOLERANCES ARE +/- .010". | DIMENSIONS ARE FOR REFERENCE ONLY. USE ARTWORK | FOR ACCURATE MEASUREMENT OF THE BOARD OUTLINE. | 8. MAX. WARP & TWIST TO BE .0075 INCHES PER INCH. | 9. ALL HOLES ARE ON A 0.0001 GRID EXCEPT THOSE | INDICATED. | ALL BOARDS MUST MEET OR EXCEED UL94V-0 REQUIREMENTS. | PCB MUST BEAR THE UL94V-0 REGISTERED MATERIAL ID NUMBER. | CONTROLLED IMPEDANCE | Primary Side Shown
User.13: 0.0042" WIDE/0.0043" SPACING 80 OHMS DIFFERENTIAL +/-10% | 0.0037" WIDE/0.0063" SPACING 100 OHMS DIFFERENTIAL +/-10% | 0.0054" WIDE/0.0046" SPACING 80 OHMS DIFFERENTIAL +/-10% | 0.00475" WIDE 40 OHMS SINGLE ENDED +/-10% | 0.008" WIDE 40 OHMS SINGLE ENDED +/-10%
User.19: DLPLCR99EVM | DLP019 | TEXAS INSTRUMENTS | Rev. F
User.31: FIGURE | FINISHED_SIZE | 12.0 | 63.0 | 60.2 | 78.7 | 146.0 | 189.0 | DRILL CHART: TOP to BOTTOM | ALL UNITS ARE IN MILS | TOLERANCE_DRILL | +3.0/-12.0 | +3.0/-3.0 | +2.0/-2.0 | PLATED | NON-PLATED | QTY | 1109 | 11 | 9 | 1 | 4
